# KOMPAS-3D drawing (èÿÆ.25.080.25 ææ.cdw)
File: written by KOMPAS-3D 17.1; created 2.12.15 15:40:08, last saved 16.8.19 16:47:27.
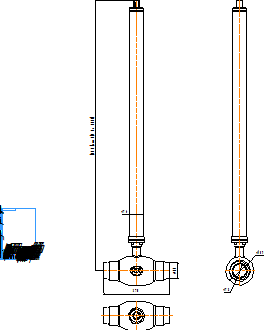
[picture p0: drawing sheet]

Sheet 1: A4, portrait

Title block, sheet 1: name: КШТ.25.080.25 С/С; sheets: 1; organisation: ООО "АДЛ Групп"; sheet format: A4; stored path: C:\Users\kka\KOMPAS_Work\Модели кранов для исследований\DN50\С удлинением\КШГ.32.050.40 СС ГЧ _ Шаровой кран БИВАЛ Ду50 Ру4 МПа редуцированный под приварку, с удлинением штока H=1100.cdw

Views: Вид 1, Проекционный вид 2
Referenced files in C:\Users\kka\KOMPAS_Work\Модели кранов для исследований\DN80\С удлинением\: КШТ.22.080.25 СС.a3d, КШГ.35.065.25 СС.a3d!КШГ.45.065.10 СС!Деталь (локальная).m3d
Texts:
  Klimkovich
  ADL
  (от 319 до 5000)
  Рама для чертежей
  Лит-Масса-Масштаб
  Материал-Предприятие
  Масштаб
  Изм.
  Лист
  № докум.
  Подп.
  Дата
  Лит.
  Разраб.
  Пров.
  Т.контр.
  Листов
  Внимание! Данный продукт является объектом авторского права ООО «Торговый Дом АДЛ».
  Запрещается изменение, копирование, распространение
  (в том числе путем копирования на другие сайты и ресурсы в Интернете)
  или любое иное использование информации и объектов без предварительного
  согласия правообладателя (ООО «Торговый Дом АДЛ»).
  Н.контр.
  Утв.
  ООО "Торговый дом АДЛ"
  Изменение
  Номер документа
  Подпись
  Обозначение документа
  Наименование изделия
  Масса изделия по ГОСТ 2.109-73
  Порядковый номер листа
  Общее количество листов в документе
  Характер работы, выполненной лицом, подписавшим документ
  Наименование или индекс предприятия, выпускающего документ
  Инв. № подл.
  Подп. и дата
  Взам. инв. №
  Инв. № дубл.
  Инвентарный номер подлинника по ГОСТ 2.501-68
  Подпись принявшего подлинник в отдел технической документации
  Инвентарный номер подлинника, взамен которого выпущен данный подлинник
  Инвентарный номер дубликата по ГОСТ 2.502-68
  Подпись принявшего дубликат в отдел технической документации
  Справ. №
  Перв. примен.
  Обозначение документа, взамен или на основании которого выпущен данный документ
  Обозначение документа, в котором впервые записан данный документ
  Подпись лица, копировавшего чертеж
  Обозначение формата листа
  !Рама для чертежа
Dimensions and other numbers on the sheet: 1500; 76; 89; 370; 78; 159; 1:1; 1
